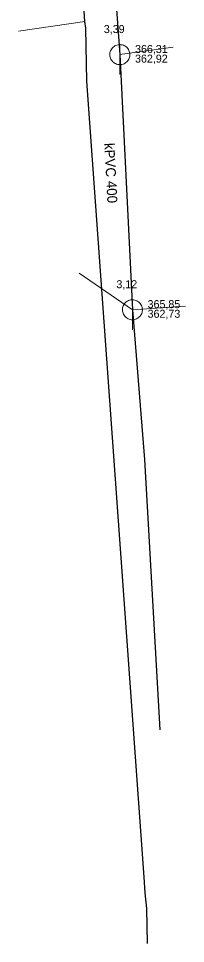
# Model space of a CAD drawing. Extents: x -809916 to -809489, y -991143 to -990912.
# Drawn here: x -809569.9 to -809553.2, y -991142.8 to -991050.4 of the extents above; entities that cross this region are included whole.
import ezdxf

# ---------------------------------------------------------------- set-up
doc = ezdxf.new("R2010")
doc.units = 0
doc.header["$LTSCALE"] = 0.32
doc.layers.add('1', color=7, linetype='Continuous')
for name, color, linetype, lineweight in [('11', 7, 'Continuous', 13), ('13', 7, 'Continuous', 13), ('14', 7, 'Continuous', 25), ('17', 7, 'Continuous', 25), ('19', 7, 'Continuous', 13), ('22', 7, 'Continuous', 13)]:
    doc.layers.add(name, color=color, linetype=linetype, lineweight=lineweight)

msp = doc.modelspace()

# ---------------------------------------------------------------- linework, layer by layer
at = {"layer": '11'}
for p, q in [((-809554.478, -991053.227), (-809559.806, -991053.969)), ((-809563.87, -991075.816), (-809558.548, -991079.472)), ((-809553.23, -991079.124), (-809558.548, -991079.472))]:
    msp.add_line(p, q, dxfattribs=at)
at = {"layer": '13'}
msp.add_line((-809563.298, -991050.671), (-809569.946, -991051.634), dxfattribs=at)
at = {"layer": '14'}
for points in [[(-809561.458, -991027.97), (-809561.357, -991029.791), (-809560.919, -991037.951), (-809560.48, -991044.932), (-809559.806, -991053.969), (-809558.548, -991079.472)], [(-809558.548, -991079.472), (-809557.322, -991094.427), (-809555.809, -991121.471)]]:
    msp.add_lwpolyline(points, dxfattribs=at)
at = {"layer": '17'}
msp.add_lwpolyline([(-809557.019, -991142.819), (-809557.113, -991139.333), (-809557.276, -991137.739), (-809557.363, -991136.19), (-809563.12, -991056.625), (-809563.21, -991051.333), (-809563.298, -991050.671), (-809563.364, -991049.635), (-809563.695, -991044.738), (-809566.549, -991012.279)], dxfattribs=at)
at = {"layer": '22'}
for p, q in [((-809559.806, -991055.969), (-809559.805, -991052.969)), ((-809558.548, -991081.472), (-809558.547, -991078.472))]:
    msp.add_line(p, q, dxfattribs=at)
for points in [[(-809558.806, -991053.969), (-809558.811, -991053.86), (-809558.829, -991053.752), (-809558.859, -991053.646), (-809558.899, -991053.545), (-809558.951, -991053.448), (-809559.013, -991053.358), (-809559.085, -991053.275), (-809559.165, -991053.201), (-809559.253, -991053.135), (-809559.347, -991053.08), (-809559.447, -991053.035), (-809559.552, -991053.002), (-809559.659, -991052.98), (-809559.768, -991052.97), (-809559.878, -991052.972), (-809559.986, -991052.986), (-809560.093, -991053.011), (-809560.196, -991053.048), (-809560.294, -991053.097), (-809560.386, -991053.155), (-809560.472, -991053.224), (-809560.549, -991053.301), (-809560.618, -991053.387), (-809560.677, -991053.479), (-809560.725, -991053.577), (-809560.762, -991053.68), (-809560.788, -991053.787), (-809560.802, -991053.895), (-809560.805, -991054.005), (-809560.795, -991054.114), (-809560.774, -991054.221), (-809560.74, -991054.325), (-809560.696, -991054.425), (-809560.641, -991054.52), (-809560.575, -991054.608), (-809560.501, -991054.688), (-809560.418, -991054.76), (-809560.328, -991054.822), (-809560.232, -991054.874), (-809560.13, -991054.915), (-809560.025, -991054.945), (-809559.917, -991054.963), (-809559.807, -991054.969), (-809559.698, -991054.963), (-809559.59, -991054.945), (-809559.485, -991054.916), (-809559.383, -991054.875), (-809559.286, -991054.823), (-809559.196, -991054.761), (-809559.113, -991054.69), (-809559.038, -991054.61), (-809558.973, -991054.522), (-809558.917, -991054.428), (-809558.873, -991054.328), (-809558.839, -991054.224), (-809558.817, -991054.116), (-809558.807, -991054.007)], [(-809557.548, -991079.472), (-809557.553, -991079.363), (-809557.571, -991079.255), (-809557.601, -991079.149), (-809557.641, -991079.048), (-809557.693, -991078.951), (-809557.755, -991078.861), (-809557.827, -991078.778), (-809557.907, -991078.704), (-809557.995, -991078.638), (-809558.089, -991078.583), (-809558.189, -991078.538), (-809558.294, -991078.505), (-809558.401, -991078.483), (-809558.51, -991078.473), (-809558.62, -991078.475), (-809558.728, -991078.489), (-809558.835, -991078.514), (-809558.938, -991078.551), (-809559.036, -991078.6), (-809559.128, -991078.658), (-809559.214, -991078.727), (-809559.291, -991078.804), (-809559.36, -991078.89), (-809559.419, -991078.982), (-809559.467, -991079.08), (-809559.504, -991079.183), (-809559.53, -991079.29), (-809559.544, -991079.398), (-809559.547, -991079.508), (-809559.537, -991079.617), (-809559.516, -991079.724), (-809559.482, -991079.828), (-809559.438, -991079.928), (-809559.383, -991080.023), (-809559.317, -991080.111), (-809559.243, -991080.191), (-809559.16, -991080.263), (-809559.07, -991080.325), (-809558.974, -991080.377), (-809558.872, -991080.418), (-809558.767, -991080.448), (-809558.659, -991080.466), (-809558.549, -991080.472), (-809558.44, -991080.466), (-809558.332, -991080.448), (-809558.227, -991080.419), (-809558.125, -991080.378), (-809558.028, -991080.326), (-809557.938, -991080.264), (-809557.855, -991080.193), (-809557.78, -991080.113), (-809557.715, -991080.025), (-809557.659, -991079.931), (-809557.615, -991079.831), (-809557.581, -991079.727), (-809557.559, -991079.619), (-809557.549, -991079.51)]]:
    msp.add_lwpolyline(points, close=True, dxfattribs=at)

# ---------------------------------------------------------------- texts
at = {"layer": '1'}
for s, p in [('3,39', (-809561.406, -991051.816)), ('3,12', (-809560.148, -991077.32))]:
    msp.add_text(s, height=0.8, dxfattribs=at).set_placement(p)
msp.add_text('kPVC 400', height=1, rotation=273, dxfattribs=at).set_placement((-809561.357, -991062.823))
at = {"layer": '19'}
for s, p in [('366,31', (-809558.284, -991053.809)), ('362,92', (-809558.284, -991054.769)), ('365,85', (-809557.026, -991079.312)), ('362,73', (-809557.026, -991080.272))]:
    msp.add_text(s, height=0.8, dxfattribs=at).set_placement(p)

doc.saveas('drawing.dxf')
